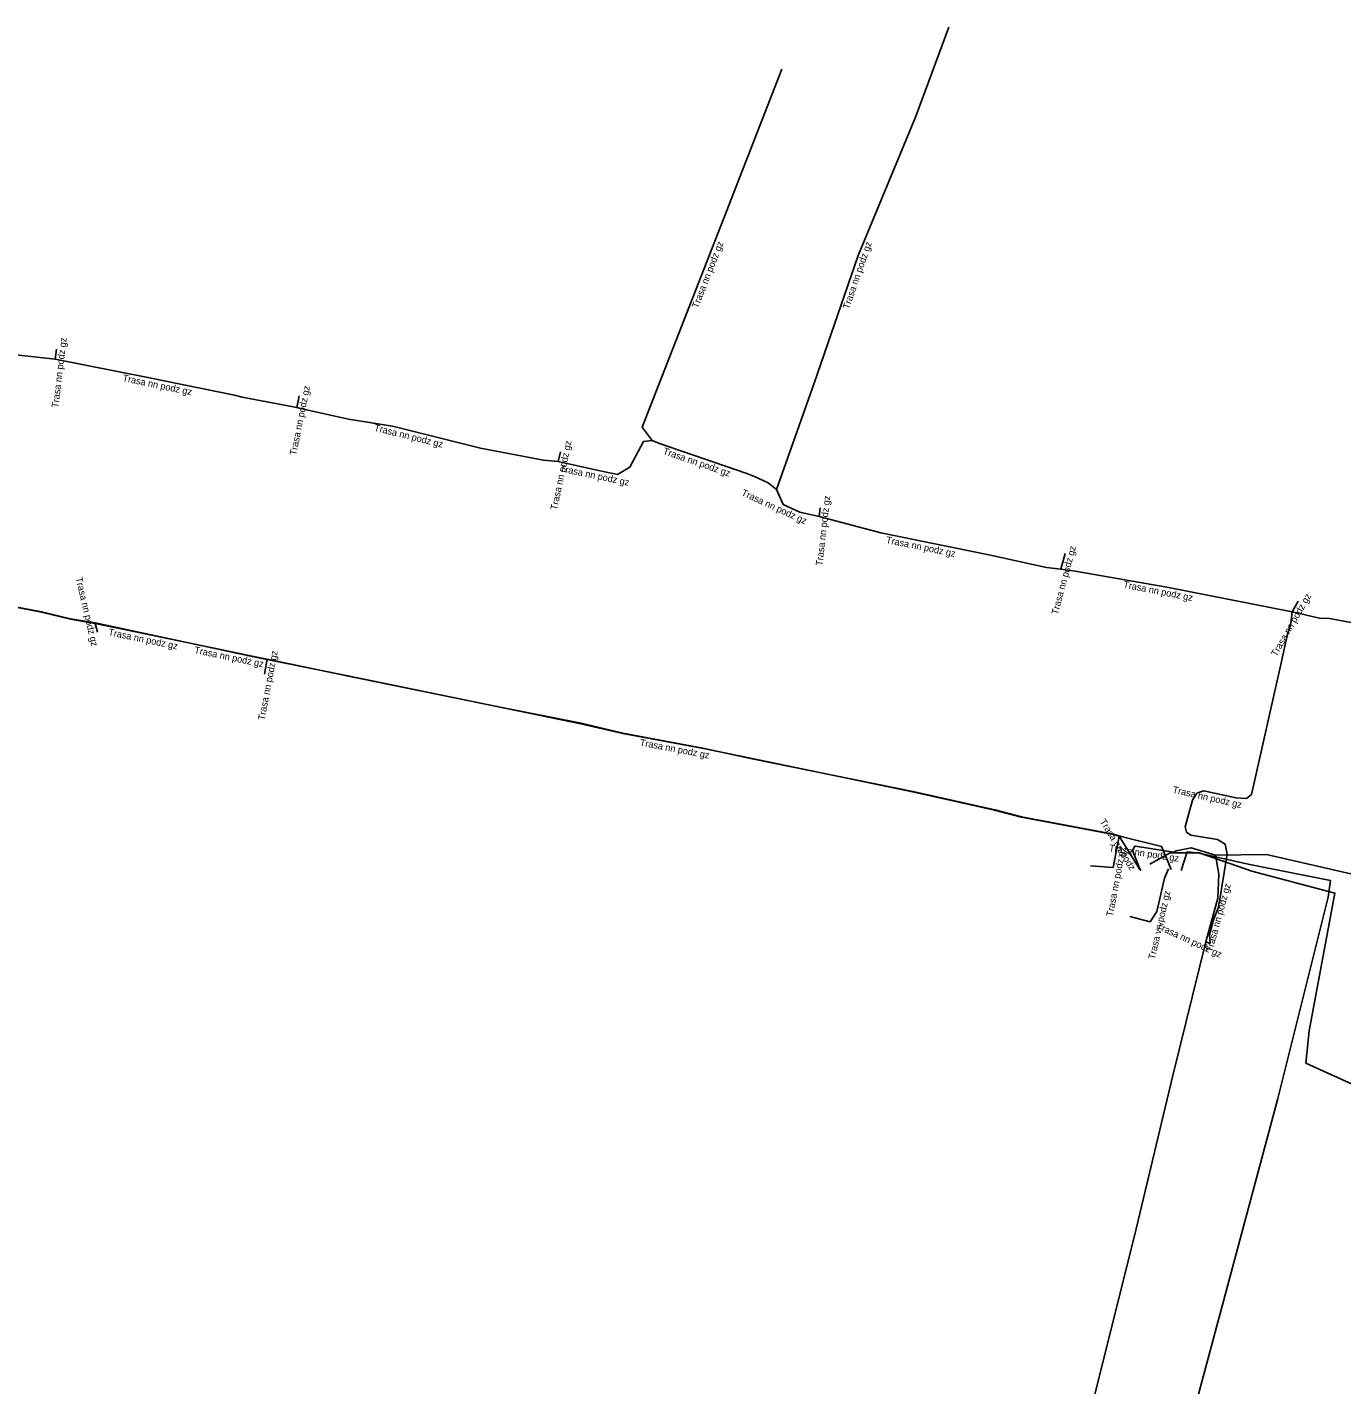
# Model space of a CAD drawing. Extents: x -687924 to -686708, y -1056742 to -1056249.
# Drawn here: x -687032.8 to -686936.7, y -1056571.5 to -1056472.2 of the extents above; entities that cross this region are included whole.
import ezdxf

# ---------------------------------------------------------------- set-up
doc = ezdxf.new("R2010")
doc.units = 0
for name, color, linetype in [('Popiskový text - Ostatní atributy Trasy', 7, 'Continuous'), ('Spojnice NN', 7, 'Continuous'), ('Spojnice VN', 7, 'Continuous')]:
    doc.layers.add(name, color=color, linetype=linetype)

msp = doc.modelspace()

# ---------------------------------------------------------------- linework, layer by layer
at = {"layer": 'Spojnice NN'}
for points in [[(-686965.41, -1056472.2), (-686967.85, -1056478.78), (-686972.04, -1056488.91), (-686975.26, -1056498.23), (-686976.51, -1056501.75), (-686978.01, -1056506.01)], [(-686977.62, -1056475.27), (-686981.87, -1056486.18), (-686987.83, -1056501.45), (-686987.1, -1056502.44)], [(-687030.75, -1056496.49), (-687034.72, -1056496.05), (-687040.39, -1056494.72), (-687049.04, -1056492.94)], [(-687030.75, -1056496.49), (-687030.66, -1056495.74)], [(-687013.09, -1056500.02), (-687017.09, -1056499.25), (-687017.65, -1056499.12), (-687023.97, -1056497.81), (-687030.75, -1056496.49)], [(-687012.92, -1056499.17), (-687013.09, -1056500.02)], [(-686993.97, -1056503.96), (-686995.06, -1056503.87), (-686999.66, -1056502.99), (-687006.1, -1056501.38), (-687009.3, -1056500.88), (-687012.81, -1056500.08), (-687013.09, -1056500.02)], [(-686987.1, -1056502.44), (-686987.75, -1056502.5), (-686988.75, -1056504.38), (-686989.65, -1056504.91), (-686991.04, -1056504.62), (-686993.97, -1056503.96)], [(-686978.01, -1056506.01), (-686978.62, -1056505.52), (-686979.57, -1056505.09), (-686980.18, -1056504.84), (-686986.58, -1056502.64), (-686987.1, -1056502.44)], [(-686993.97, -1056503.96), (-686993.82, -1056503.25)], [(-686974.9, -1056507.98), (-686976.32, -1056507.68), (-686977.54, -1056507.12), (-686978.01, -1056506.01)], [(-686974.9, -1056507.98), (-686974.83, -1056507.36)], [(-686957.22, -1056511.85), (-686958.27, -1056511.71), (-686962.5, -1056510.79), (-686970.38, -1056509.19), (-686974.9, -1056507.98)], [(-686956.91, -1056510.69), (-686957.22, -1056511.85)], [(-687045.17, -1056512.23), (-687044.887, -1056512.249), (-687038.633, -1056513.678), (-687031.767, -1056514.995), (-687029.647, -1056515.488), (-687027.82, -1056515.81)], [(-686940.31, -1056514.95), (-686949.48, -1056513.15), (-686956.17, -1056511.98), (-686957.22, -1056511.85)], [(-686939.87, -1056514.18), (-686940.31, -1056514.95)], [(-686946.32, -1056539.22), (-686946.36, -1056538.59), (-686946.06, -1056537.49), (-686945.7, -1056536.56), (-686945.06, -1056532.67), (-686945.21, -1056531.94), (-686945.77, -1056531.62), (-686947.71, -1056531.29), (-686948.03, -1056531.07), (-686948.13, -1056530.67), (-686947.61, -1056528.74), (-686947.28, -1056528.23), (-686946.78, -1056528.04), (-686944.43, -1056528.57), (-686943.64, -1056528.61), (-686943.28, -1056528.31), (-686941.1, -1056518.58), (-686940.69, -1056516.68), (-686940.41, -1056515.81), (-686940.31, -1056514.95)], [(-686940.31, -1056514.95), (-686938.31, -1056515.42), (-686937.59, -1056515.44), (-686931.28, -1056516.61), (-686923.74, -1056518.39)], [(-687027.82, -1056515.81), (-687023.582, -1056516.692), (-687018.094, -1056517.834)], [(-687027.82, -1056515.81), (-687027.67, -1056516.45)], [(-687018.094, -1056517.834), (-687016.226, -1056518.222), (-687016.003, -1056518.267), (-687015.25, -1056518.42)], [(-687015.25, -1056518.42), (-687015.46, -1056519.52)], [(-687015.25, -1056518.42), (-687009.315, -1056519.663), (-686998.46, -1056521.875), (-686992.315, -1056523.14), (-686989.255, -1056523.85), (-686983.365, -1056524.96), (-686979.79, -1056525.695), (-686967.94, -1056528.15), (-686962.067, -1056529.47), (-686960.107, -1056529.984), (-686953.385, -1056531.241), (-686952.97, -1056531.372)], [(-686952.97, -1056531.372), (-686953.401, -1056533.653), (-686955.054, -1056533.544)], [(-686952.97, -1056531.372), (-686951.443, -1056533.809), (-686951.383, -1056533.864)], [(-686951.383, -1056533.864), (-686951.44, -1056533.758), (-686951.99, -1056532.405), (-686951.805, -1056532.09), (-686951.46, -1056532.148), (-686949.133, -1056532.503), (-686948.988, -1056532.532), (-686948.797, -1056532.43), (-686947.686, -1056532.214), (-686945.918, -1056532.744)], [(-686945.918, -1056532.744), (-686945.663, -1056534.134), (-686945.742, -1056535.901), (-686946.62, -1056539.081)], [(-686945.918, -1056532.744), (-686942.18, -1056532.7), (-686930.7, -1056535.35), (-686903.35, -1056540.9), (-686888, -1056544.24), (-686870.2, -1056548.02), (-686850.81, -1056551.95), (-686831.84, -1056555.9), (-686818.08, -1056558.83), (-686813.22, -1056560.18), (-686808.29, -1056561.94), (-686791.49, -1056565.4), (-686770.93, -1056569.53)], [(-686946.62, -1056539.081), (-686949.07, -1056548.972), (-686951.721, -1056560.08), (-686956.177, -1056577.939), (-686959.315, -1056590.244), (-686964.168, -1056609.881), (-686966.363, -1056618.442), (-686970.324, -1056634.149), (-686972.152, -1056642.272), (-686975.756, -1056656.114), (-686976.767, -1056657.699), (-686976.244, -1056659.629), (-686977.248, -1056663.525), (-686977.749, -1056663.991), (-686978.304, -1056664.258)], [(-686946.62, -1056539.081), (-686946.32, -1056539.22)]]:
    msp.add_lwpolyline(points, dxfattribs=at)
at = {"layer": 'Spojnice VN'}
for points in [[(-687038.62, -1056513.64), (-687031.75, -1056514.95), (-687029.63, -1056515.46), (-687027.84, -1056515.76), (-687016.23, -1056518.24), (-687009.35, -1056519.63), (-686998.47, -1056521.88), (-686992.29, -1056523.11), (-686989.26, -1056523.82), (-686983.4, -1056524.94), (-686979.8, -1056525.7), (-686967.93, -1056528.12), (-686962.05, -1056529.45), (-686960.1, -1056529.96), (-686953.37, -1056531.23), (-686952.81, -1056531.39), (-686949.865, -1056532.112), (-686949.512, -1056532.983), (-686949.163, -1056533.797)], [(-686948.429, -1056533.87), (-686947.99, -1056532.514), (-686947.113, -1056532.601), (-686943.54, -1056533.403), (-686937.52, -1056534.61), (-686937.671, -1056535.837), (-686941.365, -1056550.553), (-686955.893, -1056604.715), (-686962.829, -1056632.194), (-686968.27, -1056654.887), (-686972.807, -1056666.077), (-686975.594, -1056668.24), (-686986.583, -1056668.035), (-687002.041, -1056664.796), (-687018.972, -1056661.27), (-687037.392, -1056656.897)], [(-686844.685, -1056568.452), (-686855.703, -1056565.874), (-686873.231, -1056562.237), (-686890.492, -1056559.141), (-686901.391, -1056556.822), (-686911.541, -1056554.926), (-686920.025, -1056553.545), (-686923.063, -1056552.631), (-686933.877, -1056550.439), (-686939.309, -1056547.959), (-686939.059, -1056545.606), (-686937.184, -1056535.526), (-686943.273, -1056533.915), (-686947.116, -1056532.591), (-686949.244, -1056532.576), (-686950.727, -1056533.421)], [(-686952.17, -1056537.23), (-686950.7, -1056537.62), (-686950.21, -1056536.87), (-686949.65, -1056534.43), (-686949.36, -1056533.75)]]:
    msp.add_lwpolyline(points, dxfattribs=at)

# ---------------------------------------------------------------- texts
at = {"layer": 'Popiskový text - Ostatní atributy Trasy'}
for s, rotation, p in [('Trasa nn podz gz', 68.67891, (-686983.755, -1056492.798)), ('Trasa nn podz gz', 70.9403, (-686972.719, -1056492.865)), ('Trasa nn podz gz', 83.15723, (-687030.524, -1056500.059)), ('Trasa nn podz gz', 348.28965, (-687025.86, -1056498.082)), ('Trasa nn podz gz', 78.69007, (-687013.131, -1056503.54)), ('Trasa nn podz gz', 345.96376, (-687007.469, -1056501.708)), ('Trasa nn podz gz', 78.07068, (-686994.064, -1056507.549)), ('Trasa nn podz gz', 341.02959, (-686986.362, -1056503.403)), ('Trasa nn podz gz', 348.21525, (-686993.887, -1056504.69)), ('Trasa nn podz gz', 335.3441, (-686980.628, -1056506.418)), ('Trasa nn podz gz', 83.5584, (-686974.656, -1056511.612)), ('Trasa nn podz gz', 348.52237, (-686970.038, -1056509.923)), ('Trasa nn podz gz', 75.03784, (-686957.443, -1056515.199)), ('Trasa nn podz gz', 283.19061, (-687029.266, -1056512.487)), ('Trasa nn podz gz', 348.89448, (-686952.692, -1056513.182)), ('Trasa nn podz gz', 60.25512, (-686941.458, -1056518.268)), ('Trasa nn podz gz', 348.24661, (-687026.901, -1056516.665)), ('Trasa nn podz gz', 348.24825, (-687020.617, -1056517.973)), ('Trasa nn podz gz', 79.19177, (-687015.447, -1056522.917)), ('Trasa nn podz gz', 349.32313, (-686988.039, -1056524.74)), ('Trasa nn podz gz', 347.29061, (-686949.086, -1056528.186)), ('Trasa nn podz', 302.06927, (-686954.407, -1056530.303)), ('Trasa nn podz gz', 79.29999, (-686953.423, -1056537.273)), ('Trasa nn podz gz', 351.32601, (-686953.727, -1056532.46)), ('Trasa nn podz gz', 74.56514, (-686946.167, -1056539.884)), ('Trasa vn podz gz', 77.074, (-686950.355, -1056540.408)), ('Trasa nn podz gz', 335.14014, (-686950.276, -1056538.103))]:
    msp.add_text(s, height=0.5, rotation=rotation, dxfattribs=at).set_placement(p)

doc.saveas('drawing.dxf')
